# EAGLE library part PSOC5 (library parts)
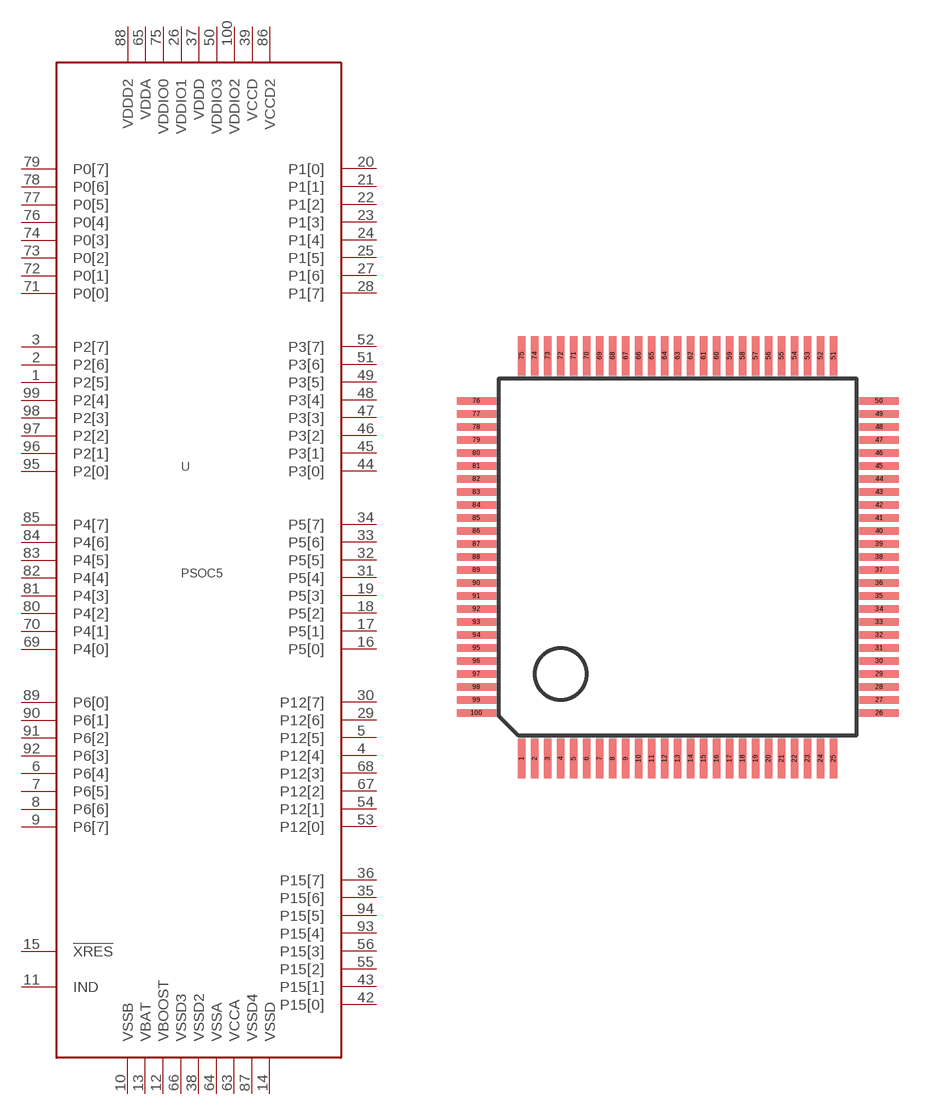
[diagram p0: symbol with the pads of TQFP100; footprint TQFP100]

Designator prefix -

## PSOC5  [TQFP100]
1  P2[5]
2  P2[6]
3  P2[7]
4  P12[4]
5  P12[5]
6  P6[4]
7  P6[5]
8  P6[6]
9  P6[7]
10  VSSB
11  IND
12  VBOOST
13  VBAT
14  VSSD
15  !XRES
16  P5[0]
17  P5[1]
18  P5[2]
19  P5[3]
20  P1[0]
21  P1[1]
22  P1[2]
23  P1[3]
24  P1[4]
25  P1[5]
26  VDDIO1
27  P1[6]
28  P1[7]
29  P12[6]
30  P12[7]
31  P5[4]
32  P5[5]
33  P5[6]
34  P5[7]
35  P15[6]
36  P15[7]
37  VDDD
38  VSSD2
39  VCCD
42  P15[0]
43  P15[1]
44  P3[0]
45  P3[1]
46  P3[2]
47  P3[3]
48  P3[4]
49  P3[5]
50  VDDIO3
51  P3[6]
52  P3[7]
53  P12[0]
54  P12[1]
55  P15[2]
56  P15[3]
63  VCCA
64  VSSA
65  VDDA
66  VSSD3
67  P12[2]
68  P12[3]
69  P4[0]
70  P4[1]
71  P0[0]
72  P0[1]
73  P0[2]
74  P0[3]
75  VDDIO0
76  P0[4]
77  P0[5]
78  P0[6]
79  P0[7]
80  P4[2]
81  P4[3]
82  P4[4]
83  P4[5]
84  P4[6]
85  P4[7]
86  VCCD2
87  VSSD4
88  VDDD2
89  P6[0]
90  P6[1]
91  P6[2]
92  P6[3]
93  P15[4]
94  P15[5]
95  P2[0]
96  P2[1]
97  P2[2]
98  P2[3]
99  P2[4]
100  VDDIO2

## Footprint TQFP100 (pad centres in mm)
Thin Quad Flat Pack
smd 0.27 x 1.5: 1 -6,-7.75; 2 -5.5,-7.75; 3 -5,-7.75; 4 -4.5,-7.75; 5 -4,-7.75; 6 -3.5,-7.75; 7 -3,-7.75; 8 -2.5,-7.75; 9 -2,-7.75; 10 -1.5,-7.75; 11 -1,-7.75; 12 -0.5,-7.75; 13 0,-7.75; 14 0.5,-7.75; 15 1,-7.75; 16 1.5,-7.75; 17 2,-7.75; 18 2.5,-7.75; 19 3,-7.75; 20 3.5,-7.75; 21 4,-7.75; 22 4.5,-7.75; 23 5,-7.75; 24 5.5,-7.75; 25 6,-7.75; 51 6,7.75; 52 5.5,7.75; 53 5,7.75; 54 4.5,7.75; 55 4,7.75; 56 3.5,7.75; 57 3,7.75; 58 2.5,7.75; 59 2,7.75; 60 1.5,7.75; 61 1,7.75; 62 0.5,7.75; 63 0,7.75; 64 -0.5,7.75; 65 -1,7.75; 66 -1.5,7.75; 67 -2,7.75; 68 -2.5,7.75; 69 -3,7.75; 70 -3.5,7.75; 71 -4,7.75; 72 -4.5,7.75; 73 -5,7.75; 74 -5.5,7.75; 75 -6,7.75
smd 1.5 x 0.27: 26 7.75,-6; 27 7.75,-5.5; 28 7.75,-5; 29 7.75,-4.5; 30 7.75,-4; 31 7.75,-3.5; 32 7.75,-3; 33 7.75,-2.5; 34 7.75,-2; 35 7.75,-1.5; 36 7.75,-1; 37 7.75,-0.5; 38 7.75,0; 39 7.75,0.5; 40 7.75,1; 41 7.75,1.5; 42 7.75,2; 43 7.75,2.5; 44 7.75,3; 45 7.75,3.5; 46 7.75,4; 47 7.75,4.5; 48 7.75,5; 49 7.75,5.5; 50 7.75,6; 76 -7.75,6; 77 -7.75,5.5; 78 -7.75,5; 79 -7.75,4.5; 80 -7.75,4; 81 -7.75,3.5; 82 -7.75,3; 83 -7.75,2.5; 84 -7.75,2; 85 -7.75,1.5; 86 -7.75,1; 87 -7.75,0.5; 88 -7.75,0; 89 -7.75,-0.5; 90 -7.75,-1; 91 -7.75,-1.5; 92 -7.75,-2; 93 -7.75,-2.5; 94 -7.75,-3; 95 -7.75,-3.5; 96 -7.75,-4; 97 -7.75,-4.5; 98 -7.75,-5; 99 -7.75,-5.5; 100 -7.75,-6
